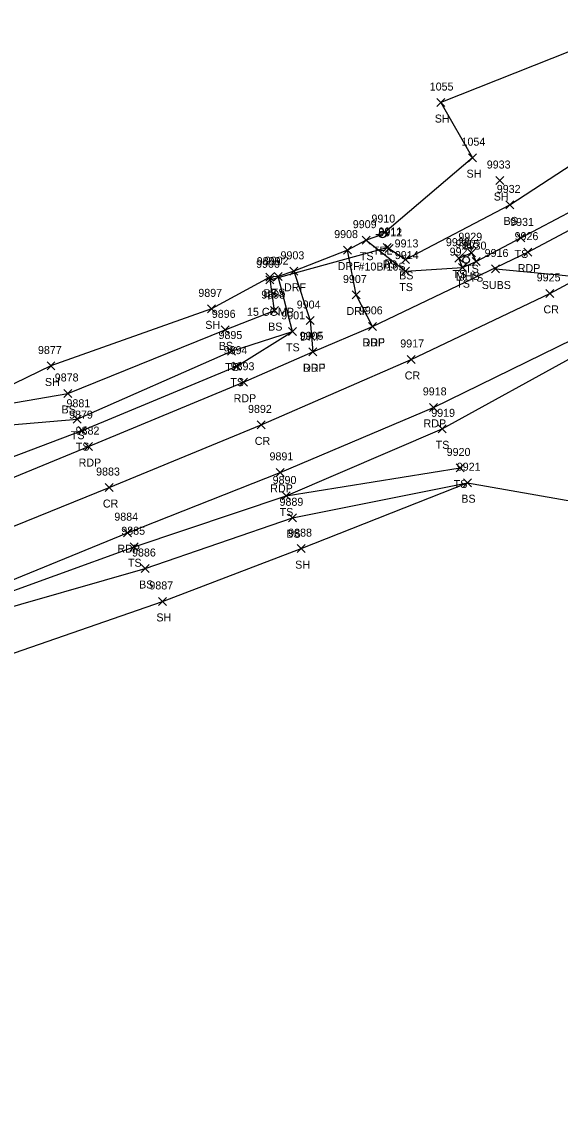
# Model space of a CAD drawing. Extents: x 1651685 to 1653558, y 889533 to 891085.
# Drawn here: x 1652207 to 1652341.8, y 889700.1 to 889970.3 of the extents above; entities that cross this region are included whole.
import ezdxf

# ---------------------------------------------------------------- set-up
doc = ezdxf.new("R2010")
doc.units = 0
for name, color, linetype in [('D_A', 7, 'Continuous'), ('D_C', 7, 'Continuous'), ('D_I', 7, 'Continuous'), ('D_TIC', 7, 'Continuous'), ('DCP', 7, 'Continuous'), ('L_A', 7, 'Continuous'), ('L_I', 7, 'Continuous'), ('L_TIC', 7, 'Continuous'), ('LELB', 7, 'Continuous'), ('LSOGP', 7, 'Continuous'), ('P_A', 7, 'Continuous'), ('P_I', 7, 'Continuous'), ('P_TIC', 7, 'Continuous'), ('PET', 7, 'Continuous'), ('PRC', 7, 'Continuous'), ('R_A', 7, 'Continuous'), ('R_I', 7, 'Continuous'), ('R_TIC', 7, 'Continuous'), ('RDF', 7, 'Continuous'), ('U_A', 7, 'Continuous'), ('U_C', 7, 'Continuous'), ('U_I', 7, 'Continuous'), ('U_TIC', 7, 'Continuous'), ('UP', 7, 'Continuous'), ('USA', 7, 'Continuous'), ('USMH', 7, 'Continuous')]:
    doc.layers.add(name, color=color, linetype=linetype)

msp = doc.modelspace()

# ---------------------------------------------------------------- linework, layer by layer
at = {"layer": 'D_TIC'}
for points in [[(1652297.44, 889912.83), (1652299.44, 889914.83)], [(1652299.44, 889912.83), (1652297.44, 889914.83)], [(1652268.12, 889904.75), (1652270.12, 889906.75)], [(1652270.12, 889904.75), (1652268.12, 889906.75)]]:
    msp.add_lwpolyline(points, dxfattribs=at)
at = {"layer": 'DCP'}
msp.add_lwpolyline([(1652269.12, 889905.75), (1652298.44, 889913.83)], dxfattribs=at)
at = {"layer": 'L_TIC'}
for points in [[(1652310.88, 889949.06), (1652312.88, 889951.06)], [(1652312.88, 889949.06), (1652310.88, 889951.06)], [(1652318.83, 889935.28), (1652320.83, 889937.28)], [(1652320.83, 889935.28), (1652318.83, 889937.28)], [(1652325.64, 889929.57), (1652327.64, 889931.57)], [(1652327.64, 889929.57), (1652325.64, 889931.57)], [(1652328.14, 889923.47), (1652330.14, 889925.47)], [(1652330.14, 889923.47), (1652328.14, 889925.47)], [(1652292.22, 889914.66), (1652294.22, 889916.66)], [(1652294.22, 889914.66), (1652292.22, 889916.66)], [(1652330.92, 889915.22), (1652332.92, 889917.22)], [(1652332.92, 889915.22), (1652330.92, 889917.22)], [(1652297.96, 889912.59), (1652299.96, 889914.59)], [(1652299.96, 889912.59), (1652297.96, 889914.59)], [(1652302.02, 889909.85), (1652304.02, 889911.85)], [(1652304.02, 889909.85), (1652302.02, 889911.85)], [(1652315.42, 889910.17), (1652317.42, 889912.17)], [(1652317.42, 889910.17), (1652315.42, 889912.17)], [(1652318.55, 889911.52), (1652320.55, 889913.52)], [(1652320.55, 889911.52), (1652318.55, 889913.52)], [(1652319.69, 889909.3), (1652321.69, 889911.3)], [(1652321.69, 889909.3), (1652319.69, 889911.3)], [(1652319.69, 889909.3), (1652321.69, 889911.3)], [(1652321.69, 889909.3), (1652319.69, 889911.3)], [(1652302.09, 889906.93), (1652304.09, 889908.93)], [(1652304.09, 889906.93), (1652302.09, 889908.93)], [(1652316.35, 889907.79), (1652318.35, 889909.79)], [(1652318.35, 889907.79), (1652316.35, 889909.79)], [(1652316.35, 889907.79), (1652318.35, 889909.79)], [(1652318.35, 889907.79), (1652316.35, 889909.79)], [(1652268.1, 889905.41), (1652270.1, 889907.41)], [(1652270.1, 889905.41), (1652268.1, 889907.41)], [(1652270.19, 889905.55), (1652272.19, 889907.55)], [(1652272.19, 889905.55), (1652270.19, 889907.55)], [(1652253.49, 889897.49), (1652255.49, 889899.49)], [(1652255.49, 889897.49), (1652253.49, 889899.49)], [(1652269.25, 889897.05), (1652271.25, 889899.05)], [(1652271.25, 889897.05), (1652269.25, 889899.05)], [(1652256.91, 889892.24), (1652258.91, 889894.24)], [(1652258.91, 889892.24), (1652256.91, 889894.24)], [(1652273.76, 889891.87), (1652275.76, 889893.87)], [(1652275.76, 889891.87), (1652273.76, 889893.87)], [(1652273.76, 889891.87), (1652275.76, 889893.87)], [(1652275.76, 889891.87), (1652273.76, 889893.87)], [(1652258.54, 889886.95), (1652260.54, 889888.95)], [(1652260.54, 889886.95), (1652258.54, 889888.95)], [(1652213.38, 889883.21), (1652215.38, 889885.21)], [(1652215.38, 889883.21), (1652213.38, 889885.21)], [(1652259.83, 889883.17), (1652261.83, 889885.17)], [(1652261.83, 889883.17), (1652259.83, 889885.17)], [(1652217.58, 889876.34), (1652219.58, 889878.34)], [(1652219.58, 889876.34), (1652217.58, 889878.34)], [(1652219.94, 889869.9), (1652221.94, 889871.9)], [(1652221.94, 889869.9), (1652219.94, 889871.9)], [(1652221.17, 889867.05), (1652223.17, 889869.05)], [(1652223.17, 889867.05), (1652221.17, 889869.05)], [(1652311.19, 889867.5), (1652313.19, 889869.5)], [(1652313.19, 889867.5), (1652311.19, 889869.5)], [(1652315.7, 889857.72), (1652317.7, 889859.72)], [(1652317.7, 889857.72), (1652315.7, 889859.72)], [(1652317.57, 889854.03), (1652319.57, 889856.03)], [(1652319.57, 889854.03), (1652317.57, 889856.03)], [(1652272.17, 889850.71), (1652274.17, 889852.71)], [(1652274.17, 889850.71), (1652272.17, 889852.71)], [(1652272.17, 889850.71), (1652274.17, 889852.71)], [(1652274.17, 889850.71), (1652272.17, 889852.71)], [(1652273.81, 889845.26), (1652275.81, 889847.26)], [(1652275.81, 889845.26), (1652273.81, 889847.26)], [(1652234.22, 889838.02), (1652236.22, 889840.02)], [(1652236.22, 889838.02), (1652234.22, 889840.02)], [(1652275.97, 889837.55), (1652277.97, 889839.55)], [(1652277.97, 889837.55), (1652275.97, 889839.55)], [(1652236.97, 889832.58), (1652238.97, 889834.58)], [(1652238.97, 889832.58), (1652236.97, 889834.58)], [(1652241.25, 889824.35), (1652243.25, 889826.35)], [(1652243.25, 889824.35), (1652241.25, 889826.35)]]:
    msp.add_lwpolyline(points, dxfattribs=at)
at = {"layer": 'LELB'}
for points in [[(1652293.22, 889915.66), (1652303.09, 889907.93), (1652317.35, 889908.79), (1652320.69, 889910.3), (1652331.92, 889916.22), (1652367.25, 889934.93), (1652401.81, 889955.3), (1652430.74, 889974.75), (1652457.46, 889995.31), (1652485.92, 890020.39), (1652507.16, 890038.54), (1652516.29, 890046.9), (1652543.45, 890076.69), (1652569.75, 890105.32), (1652598.99, 890142.55), (1652623.84, 890175.33), (1652642.78, 890202.62), (1652649.43, 890213.08), (1652650.34, 890219.8), (1652662.3, 890235.67), (1652673.05, 890250.91), (1652676.63, 890257.99), (1652674.28, 890264.42)], [(1652059.96, 889769.15), (1652077.1, 889776.34), (1652118.69, 889793.55), (1652148.83, 889805.14), (1652195.57, 889824.7), (1652235.22, 889839.02), (1652273.17, 889851.71), (1652312.19, 889868.5), (1652346.46, 889887.35), (1652384.44, 889904.89), (1652418.63, 889927.64), (1652449.26, 889948.79), (1652484.18, 889973.18), (1652505.9, 889994.66), (1652536.9, 890025.51), (1652566.28, 890055.69), (1652594.63, 890083.58), (1652622.18, 890122.04), (1652650.06, 890154.47), (1652669.87, 890181.83), (1652676.09, 890189.41), (1652687.77, 890202.23), (1652700.09, 890224.17)], [(1652298.96, 889913.59), (1652303.02, 889910.85), (1652329.14, 889924.47), (1652360.62, 889945.03)], [(1652317.35, 889908.79), (1652316.42, 889911.17), (1652319.55, 889912.52), (1652320.69, 889910.3)], [(1652104.14, 889832.31), (1652133.95, 889838.61), (1652183.13, 889853.37), (1652222.17, 889868.05), (1652260.83, 889884.17), (1652274.76, 889892.87), (1652271.19, 889906.55)], [(1652189.89, 889872.39), (1652218.58, 889877.34), (1652257.91, 889893.24), (1652270.25, 889898.05), (1652269.1, 889906.41)], [(1652200.34, 889869.13), (1652220.94, 889870.9), (1652259.54, 889887.95), (1652274.76, 889892.87)], [(1652273.17, 889851.71), (1652316.7, 889858.72)], [(1652064.04, 889766.3), (1652078.59, 889773.44), (1652119.73, 889790.45), (1652150.48, 889803.01), (1652196.54, 889821.75), (1652237.97, 889833.58), (1652274.81, 889846.26), (1652318.57, 889855.03)]]:
    msp.add_lwpolyline(points, dxfattribs=at)
at = {"layer": 'LSOGP'}
for points in [[(1652344.51, 889962.98), (1652311.88, 889950.06), (1652319.83, 889936.28), (1652297.31, 889917.06), (1652293.22, 889915.65), (1652288.54, 889913.18), (1652275.12, 889907.88), (1652271.2, 889906.55), (1652269.1, 889906.41), (1652254.49, 889898.49), (1652214.38, 889884.21), (1652189.89, 889872.39), (1652177.7, 889863.92), (1652130.38, 889845.03), (1652128.61, 889848.08), (1652100.57, 889839.31), (1652088.78, 889837.26), (1652079.97, 889838.39), (1652075.93, 889835.91), (1652046.4, 889818.27), (1652039.29, 889812.4), (1652028.35, 889807.39), (1651985.79, 889786.86)], [(1651980.89, 889713.26), (1652008.19, 889730.53), (1652031.23, 889739.86), (1652043.32, 889745.77), (1652059.06, 889752.82), (1652082.8, 889761.8), (1652098.21, 889765.57), (1652124.91, 889780.84), (1652162.24, 889787.9), (1652185.04, 889794.86), (1652201.07, 889811.05), (1652242.25, 889825.35), (1652276.97, 889838.55), (1652318.58, 889855.03), (1652374.55, 889845.16)]]:
    msp.add_lwpolyline(points, dxfattribs=at)
at = {"layer": 'P_TIC'}
for points in [[(1652332.65, 889911.67), (1652334.65, 889913.67)], [(1652334.65, 889911.67), (1652332.65, 889913.67)], [(1652338.13, 889901.36), (1652340.13, 889903.36)], [(1652340.13, 889901.36), (1652338.13, 889903.36)], [(1652293.79, 889893.11), (1652295.79, 889895.11)], [(1652295.79, 889893.11), (1652293.79, 889895.11)], [(1652278.91, 889886.76), (1652280.91, 889888.76)], [(1652280.91, 889886.76), (1652278.91, 889888.76)], [(1652303.43, 889884.84), (1652305.43, 889886.84)], [(1652305.43, 889884.84), (1652303.43, 889886.84)], [(1652261.57, 889879.14), (1652263.57, 889881.14)], [(1652263.57, 889879.14), (1652261.57, 889881.14)], [(1652309.07, 889872.86), (1652311.07, 889874.86)], [(1652311.07, 889872.86), (1652309.07, 889874.86)], [(1652265.92, 889868.48), (1652267.92, 889870.48)], [(1652267.92, 889868.48), (1652265.92, 889870.48)], [(1652222.8, 889863.06), (1652224.8, 889865.06)], [(1652224.8, 889863.06), (1652222.8, 889865.06)], [(1652270.73, 889856.62), (1652272.73, 889858.62)], [(1652272.73, 889856.62), (1652270.73, 889858.62)], [(1652227.92, 889852.82), (1652229.92, 889854.82)], [(1652229.92, 889852.82), (1652227.92, 889854.82)], [(1652232.48, 889841.54), (1652234.48, 889843.54)], [(1652234.48, 889841.54), (1652232.48, 889843.54)]]:
    msp.add_lwpolyline(points, dxfattribs=at)
at = {"layer": 'PET'}
for points in [[(1651993.09, 889770.39), (1652035.55, 889788.28), (1652064.19, 889800.06), (1652068.27, 889804.89), (1652108.23, 889818.22), (1652137.76, 889829.36), (1652185.37, 889848.31), (1652223.8, 889864.06), (1652262.57, 889880.14), (1652279.91, 889887.76), (1652294.79, 889894.11), (1652333.65, 889912.67), (1652369.12, 889931.53)], [(1651722.05, 889556.64), (1651743.79, 889579.05), (1651773.7, 889607.56), (1651801.99, 889632.45), (1651834.2, 889657.45), (1651868.37, 889681.24), (1651890.21, 889694.54), (1651910.42, 889705.67), (1651932.43, 889717.43), (1651971.73, 889735.64), (1652001.72, 889748.76), (1652035.56, 889763.08), (1652038.22, 889762.81), (1652052.59, 889768.76), (1652053.52, 889770.62), (1652076.54, 889779.88), (1652117.63, 889796.48), (1652147.54, 889808.21), (1652195.16, 889826.81), (1652233.48, 889842.54), (1652271.73, 889857.62), (1652310.07, 889873.86), (1652345.02, 889890.88)]]:
    msp.add_lwpolyline(points, dxfattribs=at)
at = {"layer": 'PRC'}
msp.add_lwpolyline([(1651712.82, 889564.71), (1651734.46, 889586.87), (1651766.27, 889617.28), (1651793.27, 889641.25), (1651826.92, 889667.91), (1651862.27, 889692.04), (1651896.77, 889712.72), (1651926.87, 889728.69), (1651966.67, 889747.09), (1651996.7, 889760.13), (1652040.05, 889778.15), (1652073.02, 889791.69), (1652113.32, 889807.56), (1652142.44, 889819.25), (1652190.37, 889838.24), (1652228.92, 889853.82), (1652266.92, 889869.48), (1652304.43, 889885.84), (1652339.13, 889902.36), (1652374.76, 889921.45)], dxfattribs=at)
at = {"layer": 'R_TIC'}
for points in [[(1652287.55, 889912.18), (1652289.55, 889914.18)], [(1652289.55, 889912.18), (1652287.55, 889914.18)], [(1652274.13, 889906.88), (1652276.13, 889908.88)], [(1652276.13, 889906.88), (1652274.13, 889908.88)], [(1652289.74, 889900.96), (1652291.74, 889902.96)], [(1652291.74, 889900.96), (1652289.74, 889902.96)], [(1652278.18, 889894.57), (1652280.18, 889896.57)], [(1652280.18, 889894.57), (1652278.18, 889896.57)], [(1652293.79, 889893.11), (1652295.79, 889895.11)], [(1652295.79, 889893.11), (1652293.79, 889895.11)], [(1652278.91, 889886.76), (1652280.91, 889888.76)], [(1652280.91, 889886.76), (1652278.91, 889888.76)]]:
    msp.add_lwpolyline(points, dxfattribs=at)
at = {"layer": 'RDF'}
for points in [[(1652294.79, 889894.11), (1652290.74, 889901.96), (1652288.55, 889913.18)], [(1652275.13, 889907.88), (1652279.18, 889895.57), (1652279.91, 889887.76)]]:
    msp.add_lwpolyline(points, dxfattribs=at)
at = {"layer": 'U_TIC'}
for points in [[(1652324.6, 889907.46), (1652326.6, 889909.46)], [(1652326.6, 889907.46), (1652324.6, 889909.46)]]:
    msp.add_lwpolyline(points, dxfattribs=at)
at = {"layer": 'UP'}
for p, q in [((1652295.65, 889917.05), (1652296.48, 889917.05)), ((1652297.31, 889917.06), (1652297.31, 889917.06)), ((1652298.98, 889917.06), (1652298.15, 889917.06)), ((1652298.15, 889917.06), (1652298.15, 889917.06)), ((1652298.98, 889917.06), (1652298.98, 889917.06))]:
    msp.add_line(p, q, dxfattribs=at)
msp.add_circle((1652297.31, 889917.06), 0.833, dxfattribs=at)
at = {"layer": 'USA'}
msp.add_lwpolyline([(1652325.6, 889908.46), (1652370.24, 889904.27)], dxfattribs=at)
at = {"layer": 'USMH'}
for p, q in [((1652318.22, 889910.71), (1652318.22, 889910.71)), ((1652319.06, 889910.71), (1652319.06, 889910.71))]:
    msp.add_line(p, q, dxfattribs=at)
msp.add_circle((1652318.22, 889910.71), 0.833, dxfattribs=at)

# ---------------------------------------------------------------- texts
at = {"layer": 'D_A'}
for p in [(1652297.82, 889908.83), (1652268.5, 889900.75)]:
    msp.add_text('P', height=2, dxfattribs=at).set_placement(p)
at = {"layer": 'D_C'}
msp.add_text('15 CGMP', height=2, dxfattribs=at).set_placement((1652263.41, 889896.75))
at = {"layer": 'D_I'}
for s, p in [('9911', (1652296.31, 889916.83)), ('9900', (1652265.69, 889908.75))]:
    msp.add_text(s, height=2, dxfattribs=at).set_placement(p)
at = {"layer": 'L_A'}
for s, p in [('SH', (1652310.37, 889945.06)), ('SH', (1652318.32, 889931.28)), ('SH', (1652325.12, 889925.57)), ('BS', (1652327.58, 889919.47)), ('TS', (1652291.63, 889910.66)), ('TS', (1652330.33, 889911.22)), ('BS', (1652297.4, 889908.59)), ('TS', (1652317.96, 889907.52)), ('BS', (1652301.46, 889905.85)), ('TS', (1652314.83, 889906.17)), ('TS', (1652315.76, 889903.79)), ('TS', (1652315.76, 889903.79)), ('TS', (1652319.1, 889905.3)), ('TS', (1652319.1, 889905.3)), ('BS', (1652267.54, 889901.41)), ('TS', (1652269.6, 889901.55)), ('TS', (1652301.5, 889902.93)), ('SH', (1652252.97, 889893.49)), ('BS', (1652268.7, 889893.05)), ('BS', (1652256.35, 889888.24)), ('TS', (1652273.17, 889887.87)), ('TS', (1652273.17, 889887.87)), ('TS', (1652257.95, 889882.95)), ('SH', (1652212.86, 889879.21)), ('TS', (1652259.24, 889879.17)), ('BS', (1652217.02, 889872.34)), ('TS', (1652219.35, 889865.9)), ('TS', (1652310.6, 889863.5)), ('TS', (1652220.58, 889863.05)), ('TS', (1652315.11, 889853.72)), ('BS', (1652317.01, 889850.03)), ('TS', (1652271.58, 889846.71)), ('TS', (1652271.58, 889846.71)), ('BS', (1652273.25, 889841.26)), ('TS', (1652233.63, 889834.02)), ('SH', (1652275.46, 889833.55)), ('BS', (1652236.41, 889828.58)), ('SH', (1652240.74, 889820.35))]:
    msp.add_text(s, height=2, dxfattribs=at).set_placement(p)
at = {"layer": 'L_I'}
for s, p in [('1055', (1652309.11, 889953.06)), ('1054', (1652317.06, 889939.28)), ('9933', (1652323.38, 889933.57)), ('9932', (1652325.88, 889927.47)), ('9909', (1652289.87, 889918.66)), ('9931', (1652329.23, 889919.22)), ('9912', (1652296.26, 889916.59)), ('9929', (1652316.28, 889915.52)), ('9913', (1652300.33, 889913.85)), ('9928', (1652313.16, 889914.17)), ('9927', (1652314.09, 889911.79)), ('9927', (1652314.09, 889911.79)), ('9930', (1652317.35, 889913.3)), ('9930', (1652317.35, 889913.3)), ('9899', (1652265.84, 889909.41)), ('9902', (1652267.85, 889909.55)), ('9914', (1652300.39, 889910.93)), ('9897', (1652251.23, 889901.49)), ('9898', (1652266.99, 889901.05)), ('9896', (1652254.6, 889896.24)), ('9901', (1652271.98, 889895.87)), ('9901', (1652271.98, 889895.87)), ('9895', (1652256.28, 889890.95)), ('9877', (1652211.12, 889887.21)), ('9894', (1652257.57, 889887.17)), ('9878', (1652215.32, 889880.34)), ('9881', (1652218.25, 889873.9)), ('9919', (1652309.49, 889871.5)), ('9879', (1652218.9, 889871.05)), ('9920', (1652313.35, 889861.72)), ('9921', (1652315.88, 889858.03)), ('9890', (1652269.82, 889854.71)), ('9890', (1652269.82, 889854.71)), ('9889', (1652271.54, 889849.26)), ('9885', (1652231.96, 889842.02)), ('9888', (1652273.71, 889841.55)), ('9886', (1652234.65, 889836.58)), ('9887', (1652238.99, 889828.35))]:
    msp.add_text(s, height=2, dxfattribs=at).set_placement(p)
at = {"layer": 'P_A'}
for s, p in [('RDP', (1652331.14, 889907.67)), ('CR', (1652337.56, 889897.36)), ('RDP', (1652292.28, 889889.11)), ('RDP', (1652277.39, 889882.76)), ('CR', (1652302.86, 889880.84)), ('RDP', (1652260.06, 889875.14)), ('RDP', (1652307.56, 889868.86)), ('CR', (1652265.35, 889864.48)), ('RDP', (1652221.29, 889859.06)), ('RDP', (1652269.22, 889852.62)), ('CR', (1652227.36, 889848.82)), ('RDP', (1652230.97, 889837.54))]:
    msp.add_text(s, height=2, dxfattribs=at).set_placement(p)
at = {"layer": 'P_I'}
for s, p in [('9926', (1652330.34, 889915.67)), ('9925', (1652335.87, 889905.36)), ('9906', (1652291.39, 889897.11)), ('9905', (1652276.57, 889890.76)), ('9917', (1652301.74, 889888.84)), ('9893', (1652259.31, 889883.14)), ('9918', (1652307.38, 889876.86)), ('9892', (1652263.66, 889872.48)), ('9882', (1652220.54, 889867.06)), ('9891', (1652269.04, 889860.62)), ('9883', (1652225.66, 889856.82)), ('9884', (1652230.22, 889845.54))]:
    msp.add_text(s, height=2, dxfattribs=at).set_placement(p)
at = {"layer": 'R_A'}
for p in [(1652286.08, 889908.18), (1652272.66, 889902.88), (1652288.28, 889896.96), (1652276.72, 889890.57), (1652292.32, 889889.11), (1652277.44, 889882.76)]:
    msp.add_text('DRF', height=2, dxfattribs=at).set_placement(p)
at = {"layer": 'R_I'}
for s, p in [('9908', (1652285.21, 889916.18)), ('9903', (1652271.79, 889910.88)), ('9907', (1652287.41, 889904.96)), ('9904', (1652275.84, 889898.57)), ('9906', (1652291.39, 889897.11)), ('9905', (1652276.57, 889890.76))]:
    msp.add_text(s, height=2, dxfattribs=at).set_placement(p)
at = {"layer": 'U_A'}
for s, p in [('TEL', (1652294.87, 889912.06)), ('MHS', (1652315.64, 889905.71)), ('SUBS', (1652322.13, 889903.46))]:
    msp.add_text(s, height=2, dxfattribs=at).set_placement(p)
at = {"layer": 'U_C'}
msp.add_text('#10B/16S', height=2, dxfattribs=at).set_placement((1652291.3, 889908.06))
at = {"layer": 'U_I'}
for s, p in [('9910', (1652294.53, 889920.06)), ('9915', (1652315.53, 889913.71)), ('9916', (1652322.85, 889911.46))]:
    msp.add_text(s, height=2, dxfattribs=at).set_placement(p)

doc.saveas('drawing.dxf')
